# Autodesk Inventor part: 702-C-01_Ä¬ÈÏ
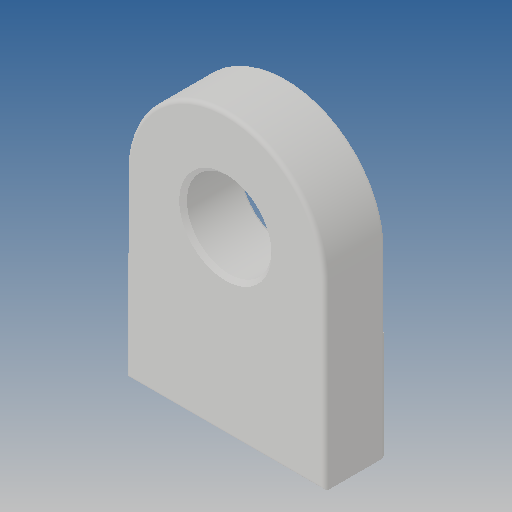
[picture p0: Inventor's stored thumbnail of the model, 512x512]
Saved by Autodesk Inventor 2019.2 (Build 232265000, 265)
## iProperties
Created: 2010-06
Part Number: 702-C-01_Ä¬ÈÏ
Material: Ogólny
Document SubType Name: Modeling
Designer: CADENGINEERING4
Density: 1 g/cm^3
Appearance: Domyślna
Author: CADENGINEERING4
Revision Number: ÈÎºÎ
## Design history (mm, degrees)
feature "NONE"
node "Bryła1"
